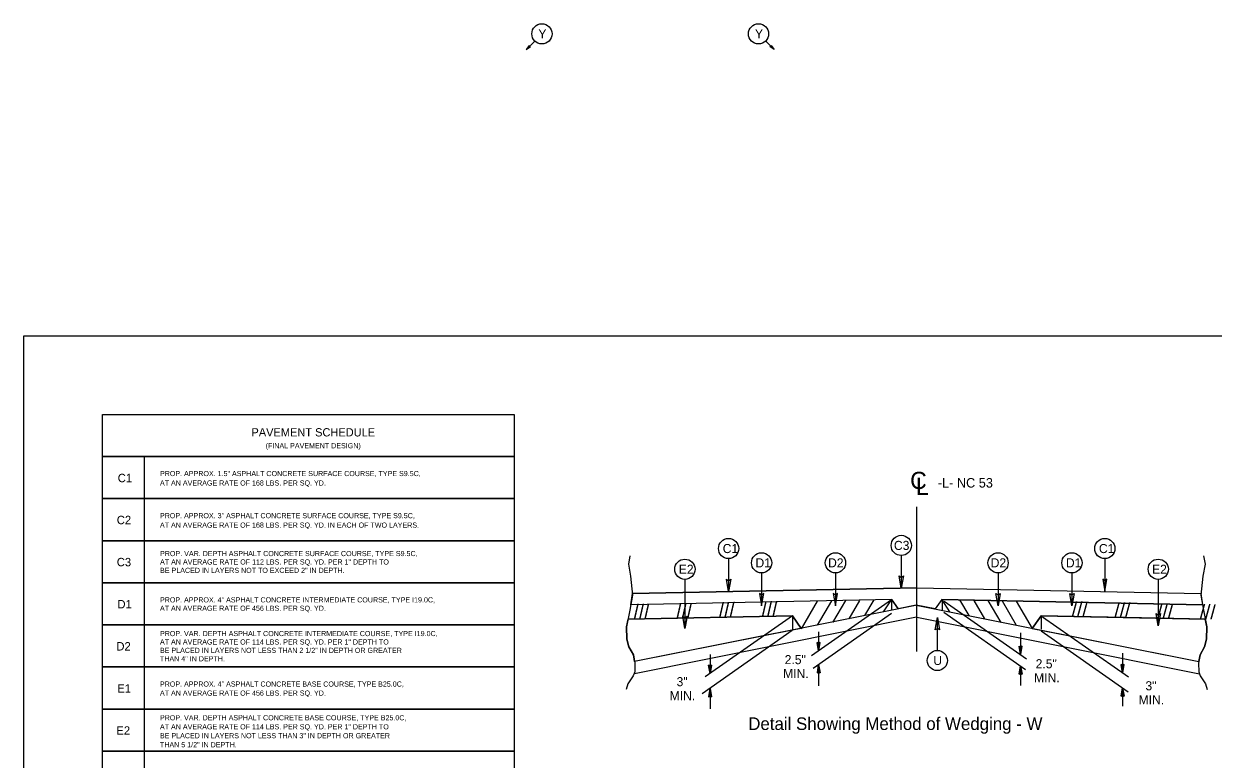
# Model space of a CAD drawing. Extents: x 1548135 to 1549339, y 868664 to 869085.
# Drawn here: x 1548135.7 to 1548249, y 869009 to 869079 of the extents above; entities that cross this region are included whole.
import ezdxf

# ---------------------------------------------------------------- set-up
doc = ezdxf.new("R2010")
doc.units = 0
doc.layers.add('Default', color=7, linetype='Continuous')
doc.layers.add('Typical Hinge Slope Interstate CELL', color=7, linetype='Continuous')

msp = doc.modelspace()

# ---------------------------------------------------------------- linework, layer by layer
at = {"layer": 'Default'}
msp.add_lwpolyline([(1548135.74, 869049.32), (1548305.74, 869049.32), (1548305.74, 868939.32), (1548135.74, 868939.32)], close=True, dxfattribs=at)
at = {"layer": 'Typical Hinge Slope Interstate CELL'}
for p, q in [((1548184.38, 869077.4), (1548183.57, 869076.6)), ((1548206.36, 869077.4), (1548207.16, 869076.6)), ((1548220.74, 869019.24), (1548220.74, 869033.03)), ((1548219.27, 869028.4), (1548219.27, 869025.28)), ((1548220.74, 869019.24), (1548220.74, 869028.66)), ((1548202.83, 869028.1), (1548202.83, 869024.97)), ((1548238.64, 869028.1), (1548238.64, 869024.97)), ((1548198.67, 869026.12), (1548198.67, 869021.44)), ((1548205.97, 869026.74), (1548205.97, 869023.62)), ((1548213, 869026.74), (1548213, 869023.62)), ((1548228.48, 869026.74), (1548228.48, 869023.62)), ((1548235.51, 869026.74), (1548235.51, 869023.62)), ((1548243.73, 869026.13), (1548243.73, 869021.69)), ((1548220.74, 869025.33), (1548193.68, 869024.79)), ((1548193.68, 869024.79), (1548220.74, 869025.33)), ((1548220.74, 869025.33), (1548247.79, 869024.79)), ((1548220.74, 869025.33), (1548247.79, 869024.79)), ((1548193.53, 869023.7), (1548193.68, 869024.79)), ((1548218.36, 869024.2), (1548193.53, 869023.7)), ((1548218.36, 869024.2), (1548193.53, 869023.7)), ((1548211.27, 869024.06), (1548209.73, 869021.42)), ((1548218.33, 869024.18), (1548210.71, 869018.84)), ((1548212.62, 869024.09), (1548211.26, 869021.75)), ((1548213.95, 869024.11), (1548212.73, 869022.02)), ((1548215.3, 869024.11), (1548214.29, 869022.38)), ((1548216.66, 869024.18), (1548215.78, 869022.67)), ((1548217.59, 869023.04), (1548218.33, 869024.19)), ((1548218.33, 869024.19), (1548218.33, 869023.25)), ((1548218.97, 869023.31), (1548218.36, 869024.2)), ((1548218.36, 869024.17), (1548218.97, 869023.31)), ((1548223.13, 869024.2), (1548222.5, 869023.31)), ((1548223.13, 869024.2), (1548222.5, 869023.31)), ((1548223.09, 869024.18), (1548223.13, 869024.18)), ((1548223.13, 869024.2), (1548247.95, 869023.7)), ((1548247.95, 869023.7), (1548223.13, 869024.2)), ((1548223.88, 869023.04), (1548223.15, 869024.19)), ((1548223.15, 869024.19), (1548223.15, 869023.15)), ((1548223.34, 869024.06), (1548231.19, 869018.56)), ((1548224.82, 869024.18), (1548225.7, 869022.67)), ((1548226.17, 869024.11), (1548227.19, 869022.38)), ((1548227.52, 869024.11), (1548228.74, 869022.02)), ((1548228.86, 869024.09), (1548230.22, 869021.75)), ((1548230.21, 869024.06), (1548231.72, 869021.46)), ((1548247.79, 869024.79), (1548247.95, 869023.7)), ((1548208.9, 869022.65), (1548193.26, 869022.34)), ((1548193.26, 869022.34), (1548208.9, 869022.65)), ((1548220.78, 869023.67), (1548193.88, 869018.29)), ((1548208.9, 869022.65), (1548200.6, 869016.84)), ((1548209.75, 869021.46), (1548208.9, 869022.65)), ((1548208.9, 869022.65), (1548208.9, 869021.29)), ((1548208.9, 869022.65), (1548209.75, 869021.46)), ((1548218.35, 869022.88), (1548210.89, 869017.65)), ((1548220.7, 869023.67), (1548218.97, 869023.31)), ((1548220.7, 869023.67), (1548247.59, 869018.29)), ((1548222.5, 869023.31), (1548220.7, 869023.67)), ((1548223.33, 869022.99), (1548231.1, 869017.54)), ((1548231.72, 869021.46), (1548232.57, 869022.65)), ((1548232.57, 869022.65), (1548231.72, 869021.46)), ((1548232.57, 869022.65), (1548248.21, 869022.34)), ((1548232.57, 869022.65), (1548232.57, 869021.39)), ((1548243.73, 869022.43), (1548232.57, 869022.65)), ((1548220.73, 869022.51), (1548193.88, 869017.14)), ((1548209.75, 869021.46), (1548208.9, 869021.29)), ((1548220.75, 869022.51), (1548247.66, 869017.13)), ((1548222.7, 869019.36), (1548222.7, 869022.48)), ((1548231.72, 869021.46), (1548235.3, 869020.75)), ((1548232.7, 869022.57), (1548240.89, 869016.83)), ((1548248.21, 869022.34), (1548243.73, 869022.43)), ((1548206.18, 869020.75), (1548193.88, 869018.29)), ((1548208.89, 869021.25), (1548200.31, 869015.21)), ((1548208.9, 869021.29), (1548206.18, 869020.75)), ((1548211.4, 869021.14), (1548211.4, 869019.33)), ((1548230.62, 869021.04), (1548230.62, 869018.96)), ((1548232.57, 869021.22), (1548240.87, 869015.41)), ((1548235.3, 869020.75), (1548247.59, 869018.29)), ((1548211.4, 869019.33), (1548211.26, 869020.12)), ((1548211.4, 869020.02), (1548211.26, 869020.12)), ((1548211.4, 869019.33), (1548211.28, 869020.11)), ((1548211.3, 869020.09), (1548211.4, 869019.33)), ((1548211.4, 869019.33), (1548211.32, 869020.08)), ((1548211.34, 869020.06), (1548211.4, 869019.33)), ((1548211.4, 869019.33), (1548211.36, 869020.05)), ((1548211.38, 869020.04), (1548211.4, 869019.33)), ((1548211.4, 869019.33), (1548211.55, 869020.12)), ((1548211.55, 869020.12), (1548211.4, 869020.02)), ((1548211.53, 869020.11), (1548211.4, 869019.33)), ((1548211.4, 869019.33), (1548211.5, 869020.09)), ((1548211.48, 869020.08), (1548211.4, 869019.33)), ((1548211.4, 869019.33), (1548211.46, 869020.06)), ((1548211.44, 869020.05), (1548211.4, 869019.33)), ((1548211.4, 869019.33), (1548211.42, 869020.04)), ((1548211.4, 869020.02), (1548211.4, 869019.33)), ((1548230.62, 869018.96), (1548230.48, 869019.75)), ((1548230.62, 869019.65), (1548230.48, 869019.75)), ((1548230.62, 869018.96), (1548230.5, 869019.74)), ((1548230.52, 869019.72), (1548230.62, 869018.96)), ((1548230.62, 869018.96), (1548230.54, 869019.71)), ((1548230.56, 869019.69), (1548230.62, 869018.96)), ((1548230.62, 869018.96), (1548230.58, 869019.68)), ((1548230.6, 869019.67), (1548230.62, 869018.96)), ((1548230.62, 869018.96), (1548230.76, 869019.75)), ((1548230.76, 869019.75), (1548230.62, 869019.65)), ((1548230.74, 869019.74), (1548230.62, 869018.96)), ((1548230.62, 869018.96), (1548230.72, 869019.72)), ((1548230.7, 869019.71), (1548230.62, 869018.96)), ((1548230.62, 869018.96), (1548230.68, 869019.69)), ((1548230.66, 869019.68), (1548230.62, 869018.96)), ((1548230.62, 869018.96), (1548230.64, 869019.67)), ((1548230.62, 869019.65), (1548230.62, 869018.96)), ((1548201.07, 869018.97), (1548201.07, 869017.17)), ((1548240.33, 869019.11), (1548240.33, 869017.23)), ((1548201.07, 869017.17), (1548200.92, 869017.96)), ((1548201.07, 869017.86), (1548200.92, 869017.96)), ((1548201.07, 869017.17), (1548200.94, 869017.95)), ((1548200.97, 869017.93), (1548201.07, 869017.17)), ((1548201.07, 869017.17), (1548200.99, 869017.92)), ((1548201.01, 869017.9), (1548201.07, 869017.17)), ((1548201.07, 869017.17), (1548201.03, 869017.89)), ((1548201.05, 869017.87), (1548201.07, 869017.17)), ((1548201.07, 869017.17), (1548201.21, 869017.96)), ((1548201.21, 869017.96), (1548201.07, 869017.86)), ((1548201.19, 869017.95), (1548201.07, 869017.17)), ((1548201.07, 869017.17), (1548201.17, 869017.93)), ((1548201.15, 869017.92), (1548201.07, 869017.17)), ((1548201.07, 869017.17), (1548201.13, 869017.9)), ((1548201.11, 869017.89), (1548201.07, 869017.17)), ((1548201.07, 869017.17), (1548201.09, 869017.87)), ((1548201.07, 869017.86), (1548201.07, 869017.17)), ((1548211.4, 869018.01), (1548211.26, 869017.22)), ((1548211.26, 869017.22), (1548211.4, 869017.32)), ((1548211.28, 869017.23), (1548211.4, 869018.01)), ((1548211.4, 869018.01), (1548211.3, 869017.25)), ((1548211.32, 869017.26), (1548211.4, 869018.01)), ((1548211.4, 869018.01), (1548211.34, 869017.28)), ((1548211.36, 869017.29), (1548211.4, 869018.01)), ((1548211.4, 869018.01), (1548211.38, 869017.3)), ((1548211.4, 869018.01), (1548211.4, 869015.97)), ((1548211.4, 869018.01), (1548211.55, 869017.22)), ((1548211.4, 869017.32), (1548211.4, 869018.01)), ((1548211.42, 869017.3), (1548211.4, 869018.01)), ((1548211.4, 869018.01), (1548211.44, 869017.29)), ((1548211.46, 869017.28), (1548211.4, 869018.01)), ((1548211.4, 869018.01), (1548211.48, 869017.26)), ((1548211.5, 869017.25), (1548211.4, 869018.01)), ((1548211.4, 869018.01), (1548211.53, 869017.23)), ((1548211.4, 869017.32), (1548211.55, 869017.22)), ((1548230.62, 869017.88), (1548230.48, 869017.09)), ((1548230.48, 869017.09), (1548230.62, 869017.19)), ((1548230.5, 869017.1), (1548230.62, 869017.88)), ((1548230.62, 869017.88), (1548230.52, 869017.12)), ((1548230.54, 869017.13), (1548230.62, 869017.88)), ((1548230.62, 869017.88), (1548230.56, 869017.15)), ((1548230.58, 869017.16), (1548230.62, 869017.88)), ((1548230.62, 869017.88), (1548230.6, 869017.18)), ((1548230.62, 869017.88), (1548230.62, 869016.02)), ((1548230.62, 869017.88), (1548230.76, 869017.09)), ((1548230.62, 869017.19), (1548230.62, 869017.88)), ((1548230.64, 869017.18), (1548230.62, 869017.88)), ((1548230.62, 869017.88), (1548230.66, 869017.16)), ((1548230.68, 869017.15), (1548230.62, 869017.88)), ((1548230.62, 869017.88), (1548230.7, 869017.13)), ((1548230.72, 869017.12), (1548230.62, 869017.88)), ((1548230.62, 869017.88), (1548230.74, 869017.1)), ((1548230.62, 869017.19), (1548230.76, 869017.09)), ((1548240.33, 869017.23), (1548240.19, 869018.02)), ((1548240.33, 869017.92), (1548240.19, 869018.02)), ((1548240.33, 869017.23), (1548240.21, 869018.01)), ((1548240.23, 869017.99), (1548240.33, 869017.23)), ((1548240.33, 869017.23), (1548240.25, 869017.98)), ((1548240.27, 869017.96), (1548240.33, 869017.23)), ((1548240.33, 869017.23), (1548240.29, 869017.95)), ((1548240.3, 869017.93), (1548240.33, 869017.23)), ((1548240.33, 869017.23), (1548240.47, 869018.02)), ((1548240.47, 869018.02), (1548240.33, 869017.92)), ((1548240.45, 869018.01), (1548240.33, 869017.23)), ((1548240.33, 869017.23), (1548240.43, 869017.99)), ((1548240.41, 869017.98), (1548240.33, 869017.23)), ((1548240.33, 869017.23), (1548240.39, 869017.96)), ((1548240.37, 869017.95), (1548240.33, 869017.23)), ((1548240.33, 869017.23), (1548240.35, 869017.93)), ((1548240.33, 869017.92), (1548240.33, 869017.23)), ((1548240.33, 869015.79), (1548240.19, 869015)), ((1548240.21, 869015.01), (1548240.33, 869015.79)), ((1548240.33, 869015.79), (1548240.23, 869015.03)), ((1548240.25, 869015.04), (1548240.33, 869015.79)), ((1548240.33, 869015.79), (1548240.27, 869015.06)), ((1548240.29, 869015.07), (1548240.33, 869015.79)), ((1548240.33, 869015.79), (1548240.3, 869015.08)), ((1548240.33, 869015.79), (1548240.33, 869014.05)), ((1548240.33, 869015.79), (1548240.47, 869015)), ((1548240.33, 869015.1), (1548240.33, 869015.79)), ((1548240.35, 869015.08), (1548240.33, 869015.79)), ((1548240.33, 869015.79), (1548240.37, 869015.07)), ((1548240.39, 869015.06), (1548240.33, 869015.79)), ((1548240.33, 869015.79), (1548240.41, 869015.04)), ((1548240.43, 869015.03), (1548240.33, 869015.79)), ((1548240.33, 869015.79), (1548240.45, 869015.01)), ((1548201.07, 869015.74), (1548200.92, 869014.94)), ((1548200.92, 869014.94), (1548201.07, 869015.04)), ((1548200.95, 869014.96), (1548201.07, 869015.74)), ((1548201.07, 869015.74), (1548200.97, 869014.97)), ((1548200.99, 869014.99), (1548201.07, 869015.74)), ((1548201.07, 869015.74), (1548201.01, 869015)), ((1548201.03, 869015.01), (1548201.07, 869015.74)), ((1548201.07, 869015.74), (1548201.05, 869015.03)), ((1548201.07, 869015.74), (1548201.07, 869013.8)), ((1548201.07, 869015.74), (1548201.21, 869014.94)), ((1548201.07, 869015.04), (1548201.07, 869015.74)), ((1548201.09, 869015.03), (1548201.07, 869015.74)), ((1548201.07, 869015.74), (1548201.11, 869015.01)), ((1548201.13, 869015), (1548201.07, 869015.74)), ((1548201.07, 869015.74), (1548201.15, 869014.99)), ((1548201.17, 869014.97), (1548201.07, 869015.74)), ((1548201.07, 869015.74), (1548201.19, 869014.96)), ((1548201.07, 869015.04), (1548201.21, 869014.94)), ((1548240.19, 869015), (1548240.33, 869015.1)), ((1548240.33, 869015.1), (1548240.47, 869015))]:
    msp.add_line(p, q, dxfattribs=at)
for points in [[(1548183.85, 869076.99), (1548183.57, 869076.6), (1548183.97, 869076.87), (1548183.86, 869076.89)], [(1548206.88, 869076.99), (1548207.16, 869076.6), (1548206.77, 869076.87), (1548206.87, 869076.89)], [(1548143.22, 869041.83), (1548182.42, 869041.83), (1548182.42, 869037.83), (1548143.22, 869037.83)], [(1548203.04, 869026.15), (1548202.83, 869024.97), (1548202.63, 869026.15), (1548202.83, 869026)], [(1548203.04, 869026.15), (1548202.83, 869024.97), (1548202.63, 869026.15), (1548202.83, 869026)], [(1548219.47, 869026.45), (1548219.27, 869025.28), (1548219.06, 869026.45), (1548219.27, 869026.3)], [(1548219.47, 869026.45), (1548219.27, 869025.28), (1548219.06, 869026.45), (1548219.27, 869026.3)], [(1548238.44, 869026.15), (1548238.64, 869024.97), (1548238.85, 869026.15), (1548238.64, 869026)], [(1548238.44, 869026.15), (1548238.64, 869024.97), (1548238.85, 869026.15), (1548238.64, 869026)], [(1548205.76, 869024.79), (1548205.97, 869023.62), (1548206.17, 869024.79), (1548205.97, 869024.64)], [(1548212.79, 869024.79), (1548213, 869023.62), (1548213.2, 869024.79), (1548213, 869024.64)], [(1548212.79, 869024.79), (1548213, 869023.62), (1548213.2, 869024.79), (1548213, 869024.64)], [(1548228.68, 869024.79), (1548228.48, 869023.62), (1548228.27, 869024.79), (1548228.48, 869024.64)], [(1548228.68, 869024.79), (1548228.48, 869023.62), (1548228.27, 869024.79), (1548228.48, 869024.64)], [(1548235.71, 869024.79), (1548235.51, 869023.62), (1548235.3, 869024.79), (1548235.51, 869024.64)], [(1548235.71, 869024.79), (1548235.51, 869023.62), (1548235.3, 869024.79), (1548235.51, 869024.64)], [(1548198.88, 869022.61), (1548198.67, 869021.44), (1548198.47, 869022.62), (1548198.67, 869022.47)], [(1548243.93, 869022.86), (1548243.73, 869021.69), (1548243.52, 869022.86), (1548243.73, 869022.71)], [(1548198.75, 869021.91), (1548198.67, 869021.44), (1548198.59, 869021.91), (1548198.67, 869021.85)], [(1548222.49, 869021.31), (1548222.7, 869022.48), (1548222.9, 869021.31), (1548222.7, 869021.46)], [(1548222.49, 869021.31), (1548222.7, 869022.48), (1548222.9, 869021.31), (1548222.7, 869021.46)]]:
    msp.add_lwpolyline(points, close=True, dxfattribs=at)
for points in [[(1548147.23, 869033.82), (1548143.22, 869033.82), (1548143.22, 869037.83), (1548182.42, 869037.83), (1548182.42, 869033.82), (1548147.23, 869033.82), (1548147.23, 869037.83)], [(1548147.23, 869029.81), (1548143.22, 869029.81), (1548143.22, 869033.82), (1548182.42, 869033.82), (1548182.42, 869029.81), (1548147.23, 869029.81), (1548147.23, 869033.82)], [(1548147.23, 869025.8), (1548143.22, 869025.8), (1548143.22, 869029.81), (1548182.42, 869029.81), (1548182.42, 869025.8), (1548147.23, 869025.8), (1548147.23, 869029.81)], [(1548193.43, 869028.36), (1548193.29, 869027.57), (1548193.5, 869026.44), (1548193.69, 869024.62), (1548193.43, 869023.18), (1548193.12, 869021.62), (1548193.14, 869020.44), (1548193.33, 869019.7), (1548193.77, 869018.95), (1548193.91, 869018.14), (1548193.89, 869017.32), (1548193.74, 869016.94), (1548193.24, 869016.17), (1548193.07, 869015.64)], [(1548248.04, 869028.36), (1548248.19, 869027.57), (1548247.97, 869026.44), (1548247.78, 869024.62), (1548248.04, 869023.18), (1548248.36, 869021.62), (1548248.33, 869020.44), (1548248.14, 869019.7), (1548247.71, 869018.95), (1548247.56, 869018.14), (1548247.59, 869017.32), (1548247.73, 869016.94), (1548248.24, 869016.17), (1548248.4, 869015.64)], [(1548147.23, 869021.79), (1548143.22, 869021.79), (1548143.22, 869025.8), (1548182.42, 869025.8), (1548182.42, 869021.79), (1548147.23, 869021.79), (1548147.23, 869025.8)], [(1548147.23, 869017.78), (1548143.22, 869017.78), (1548143.22, 869021.79), (1548182.42, 869021.79), (1548182.42, 869017.78), (1548147.23, 869017.78), (1548147.23, 869021.79)], [(1548193.88, 869018.29), (1548193.77, 869018.95), (1548193.33, 869019.7), (1548193.14, 869020.44), (1548193.12, 869021.62), (1548193.26, 869022.34)], [(1548247.59, 869018.29), (1548247.71, 869018.95), (1548248.14, 869019.7), (1548248.33, 869020.44), (1548248.36, 869021.62), (1548248.21, 869022.34)], [(1548147.23, 869013.77), (1548143.22, 869013.77), (1548143.22, 869017.78), (1548182.42, 869017.78), (1548182.42, 869013.77), (1548147.23, 869013.77), (1548147.23, 869017.78)], [(1548147.23, 869009.76), (1548143.22, 869009.76), (1548143.22, 869013.77), (1548182.42, 869013.77), (1548182.42, 869009.76), (1548147.23, 869009.76), (1548147.23, 869013.77)], [(1548147.23, 869005.75), (1548143.22, 869005.75), (1548143.22, 869009.76), (1548182.42, 869009.76), (1548182.42, 869005.75), (1548147.23, 869005.75), (1548147.23, 869009.76)]]:
    msp.add_lwpolyline(points, dxfattribs=at)
for centre in [(1548185.06, 869078.08), (1548205.68, 869078.08), (1548202.83, 869029.06), (1548219.27, 869029.36), (1548238.64, 869029.06), (1548205.97, 869027.7), (1548213, 869027.7), (1548228.48, 869027.7), (1548235.51, 869027.7), (1548198.67, 869027.09), (1548243.73, 869027.09), (1548222.7, 869018.4)]:
    msp.add_circle(centre, 0.962, dxfattribs=at)

# ---------------------------------------------------------------- texts
for s, height, p in [('Y', 0.861, (1548184.72, 869077.65)), ('Y', 0.861, (1548205.34, 869077.65)), ('PAVEMENT SCHEDULE', 0.784, (1548157.41, 869039.74)), ('(FINAL PAVEMENT DESIGN)', 0.49, (1548158.76, 869038.61)), ('C1', 0.8, (1548144.68, 869035.38)), ('PROP. APPROX. 1.5" ASPHALT CONCRETE SURFACE COURSE, TYPE S9.5C,', 0.49, (1548148.7, 869035.96)), ('C', 1.64, (1548220.11, 869034.73)), ('AT AN AVERAGE RATE OF 168 LBS. PER SQ. YD.', 0.49, (1548148.7, 869035.06)), ('-L- NC 53', 0.904, (1548222.75, 869034.87)), ('C2', 0.8, (1548144.59, 869031.38)), ('PROP. APPROX. 3" ASPHALT CONCRETE SURFACE COURSE, TYPE S9.5C,', 0.49, (1548148.7, 869031.95)), ('AT AN AVERAGE RATE OF 168 LBS. PER SQ. YD. IN EACH OF TWO LAYERS.', 0.49, (1548148.7, 869031.05)), ('C1', 0.861, (1548202.27, 869028.63)), ('C3', 0.861, (1548218.57, 869028.93)), ('C1', 0.861, (1548238.08, 869028.63)), ('PROP. VAR. DEPTH ASPHALT CONCRETE SURFACE COURSE, TYPE S9.5C,', 0.49, (1548148.71, 869028.34)), ('C3', 0.8, (1548144.59, 869027.37)), ('AT AN AVERAGE RATE OF 112 LBS. PER SQ. YD. PER 1" DEPTH TO', 0.49, (1548148.71, 869027.54)), ('BE PLACED IN LAYERS NOT TO EXCEED 2" IN DEPTH.', 0.49, (1548148.71, 869026.74)), ('E2', 0.861, (1548198.09, 869026.66)), ('D1', 0.861, (1548205.39, 869027.27)), ('D2', 0.861, (1548212.3, 869027.27)), ('D2', 0.861, (1548227.78, 869027.27)), ('D1', 0.861, (1548234.94, 869027.27)), ('E2', 0.861, (1548243.14, 869026.66)), ('D1', 0.8, (1548144.65, 869023.36)), ('PROP. APPROX. 4" ASPHALT CONCRETE INTERMEDIATE COURSE, TYPE I19.0C,', 0.49, (1548148.7, 869023.93)), ('AT AN AVERAGE RATE OF 456 LBS. PER SQ. YD.', 0.49, (1548148.7, 869023.13)), ('AT AN AVERAGE RATE OF 114 LBS. PER SQ. YD. PER 1" DEPTH TO', 0.49, (1548148.7, 869019.92)), ('PROP. VAR. DEPTH ASPHALT CONCRETE INTERMEDIATE COURSE, TYPE I19.0C,', 0.49, (1548148.7, 869020.72)), ('D2', 0.8, (1548144.55, 869019.35)), ('BE PLACED IN LAYERS NOT LESS THAN 2 1/2" IN DEPTH OR GREATER', 0.49, (1548148.7, 869019.12)), ('THAN 4" IN DEPTH.', 0.49, (1548148.7, 869018.32)), ('2.5"', 0.861, (1548208.17, 869018.05)), ('U', 0.861, (1548222.32, 869017.97)), ('2.5"', 0.861, (1548232.06, 869017.66)), ('MIN.', 0.861, (1548208.02, 869016.72)), ('MIN.', 0.861, (1548231.91, 869016.33)), ('E1', 0.784, (1548144.65, 869015.35)), ('PROP. APPROX. 4" ASPHALT CONCRETE BASE COURSE, TYPE B25.0C,', 0.49, (1548148.7, 869015.91)), ('3"', 0.861, (1548197.88, 869015.95)), ('3"', 0.861, (1548242.51, 869015.56)), ('AT AN AVERAGE RATE OF 456 LBS. PER SQ. YD.', 0.49, (1548148.7, 869015.05)), ('MIN.', 0.861, (1548197.22, 869014.62)), ('MIN.', 0.861, (1548241.86, 869014.23)), ('PROP. VAR. DEPTH ASPHALT CONCRETE BASE COURSE, TYPE B25.0C,', 0.49, (1548148.7, 869012.7)), ('Detail Showing Method of Wedging - W', 1.2, (1548204.7, 869011.78)), ('E2', 0.8, (1548144.55, 869011.33)), ('AT AN AVERAGE RATE OF 114 LBS. PER SQ. YD. PER 1" DEPTH TO', 0.49, (1548148.7, 869011.84)), ('BE PLACED IN LAYERS NOT LESS THAN 3" IN DEPTH OR GREATER', 0.49, (1548148.7, 869010.99)), ('THAN 5 1/2" IN DEPTH.', 0.49, (1548148.7, 869010.13))]:
    msp.add_text(s, height=height, dxfattribs=at).set_placement(p)
for s, height, rotation, p in [('L', 1.64, 359.9469, (1548220.66, 869034.17)), ('/// ', 1.357, 1.1447, (1548193.8, 869022.36)), ('/// ', 1.357, 1.1464, (1548197.86, 869022.41)), ('/// ', 1.356, 1.1445, (1548201.92, 869022.53)), ('/// ', 1.356, 1.1463, (1548205.99, 869022.61)), ('/// ', 1.356, 358.8553, (1548235.49, 869022.61)), ('/// ', 1.356, 358.8536, (1548239.55, 869022.53)), ('/// ', 1.357, 358.8554, (1548243.62, 869022.41)), ('/// ', 1.357, 358.8537, (1548247.67, 869022.36))]:
    msp.add_text(s, height=height, rotation=rotation, dxfattribs=at).set_placement(p)

doc.saveas('drawing.dxf')
